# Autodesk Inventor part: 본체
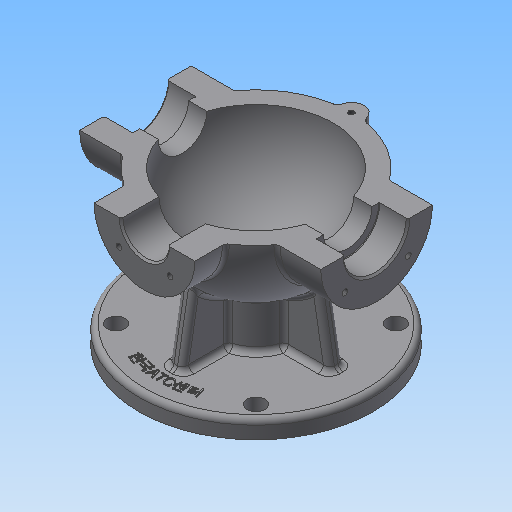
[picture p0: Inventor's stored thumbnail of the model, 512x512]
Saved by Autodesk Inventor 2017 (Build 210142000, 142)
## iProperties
Created: 2015-12
Part Number: 본체
Material: 일반
Document SubType Name: Modeling
Designer: mduedu
Density: 2.71 g/cm^3
Appearance: 기본값
Author: mduedu
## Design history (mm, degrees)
sketch "스케치1"
  geometry: L1 (-53, 0)-(53, 0); A1 r 53 centre (0, 0) between (53, 0) and (-53, 0); 2 further points
  constraints: 2 coincident, 2 end point, 2 point on circle, 1 centre point, 1 horizontal, 1 midpoint
  dimensions: "d0" = 53 radius of A1
revolve "회전1" sketch "스케치1" stored, may be unused: angle "d2" = 90 deg
feature "쉘1" dims "d11" = 10
node "작업 평면1"
sketch "스케치2"
  geometry: C1 r 31 at (0, 0); 1 further point
  constraints: 1 centre point, 1 coincident
  dimensions: "d4" = 62 diameter of C1
extrude "돌출1" join sketch "스케치2" stored distance "d5" = 10; taper "d6" = 0 deg
node "작업 평면2"
sketch "스케치3"
  geometry: C1 r 28 at (0, 0); 1 further point
  constraints: 1 centre point, 1 coincident
  dimensions: "d8" = 56 diameter of C1
extrude "돌출2" join sketch "스케치3" stored distance "d9" = 10; taper "d10" = 0 deg
hole "구멍1" diameter "d14" = 35; stored, may be unused: countersink angle "d18" = 90 deg, drill point angle "d20" = 0 deg; dims "d12" = 10, "d13" = 10, "d15" = 6, "d16" = 4, "d17" = 2, "d19" = 16
hole "구멍2" diameter "d23" = 27; stored, may be unused: countersink angle "d27" = 90 deg, drill point angle "d29" = 0 deg; dims "d21" = 10, "d22" = 10, "d24" = 6, "d25" = 4, "d26" = 2, "d28" = 16
fillet "모깎기1" dims "d30" = 0.3
hole "구멍3" diameter "d33" = 26; stored, may be unused: countersink angle "d37" = 90 deg, drill point angle "d39" = 0 deg; dims "d31" = 10, "d32" = 10, "d34" = 6, "d35" = 4, "d36" = 2, "d38" = 16
chamfer "모따기1" distance "d40" = 1; stored, may be unused: second distance "d41" = 2, angle "d42" = 45 deg
sketch "스케치4"
  geometry: L1 (0, 0)-(0, -25); L2 (0, 0)-(-17.678, -17.678); A1 r 25 centre (0, 0) between (-17.678, -17.678) and (0, -25); 1 further point
  constraints: 4 end point, 2 point on circle, 1 centre point, 1 coincident, 1 vertical
  dimensions: "d43" = 50 diameter of A1; "d47" = 45 deg angle of L1 L2
hole "구멍4" sketch "스케치4" at (-17.678, -17.678) diameter "d49" = 3.242; stored, may be unused: countersink angle "d53" = 90 deg, drill point angle "d55" = 118 deg; dims "d50" = 11, "d51" = 4, "d52" = 2, "d54" = 13
sketch "스케치5"
  geometry: L1 (0, 0)-(0, -20); L2 (0, 0)-(-14.142, -14.142); A1 r 20 centre (0, 0) between (0, -20) and (-14.142, -14.142); 2 further points
  constraints: 4 end point, 2 coincident, 2 point on circle, 1 centre point, 1 vertical
  dimensions: "d59" = 40 diameter of A1; "d65" = 45 deg angle of L1 L2
hole "구멍5" sketch "스케치5" at (-14.142, -14.142) diameter "d67" = 3.242; stored, may be unused: countersink angle "d71" = 90 deg, drill point angle "d73" = 118 deg; dims "d68" = 8, "d69" = 4, "d70" = 2, "d72" = 10
node "작업 평면3"
sketch "스케치6"
  geometry: C1 r 65 at (0, 0); 1 further point
  constraints: 1 centre point, 1 coincident
  dimensions: "d78" = 130 diameter of C1
extrude "돌출3" join sketch "스케치6" distance "d80" = 10; taper "d81" = 0 deg
sketch "스케치7"
  geometry: C1 r 20 at (0, 0); 1 further point
  constraints: 1 centre point, 1 coincident
  dimensions: "d82" = 40 diameter of C1
extrude "돌출4" join sketch "스케치7" stored distance "d84" = 10; taper "d85" = 0 deg
sketch "스케치8"
  geometry: 2 further points
  constraints: 1 coincident
hole "구멍6" sketch "스케치8" at (0, 0) diameter "d86" = 20; stored, may be unused: countersink angle "d90" = 90 deg, drill point angle "d92" = 118 deg; dims "d87" = 7, "d88" = 40, "d89" = 5, "d91" = 10
fillet "모깎기2" dims "d93" = 0.3
sketch "스케치9"
  geometry: L1 (65, -75)-(-65, -75) reference; L2 (-45, -75)-(-38.245, -36.692); A1 r 53 centre (0, 0) between (42.988, 31) and (42.988, -31) reference; 1 further point
  constraints: 2 end point, 1 point on circle, 1 point on line
  dimensions: "d94" = 45 horizontal distance of L2.start point (0, 0); "d95" = 80 deg angle of L2 L1
feature "리브1" sketch "스케치9" dims "d96" = 1, "d97" = 8, "d98" = 0, "d99" = 0, "d100" = 1, "d101" = 1
sketch "스케치10"
  geometry: L1 (0, 0)-(0, -55); L2 (0, 0)-(-38.891, -38.891); A1 r 55 centre (0, 0) between (0, -55) and (-38.891, -38.891); 2 further points
  constraints: 4 end point, 2 coincident, 2 point on circle, 1 centre point, 1 vertical
  dimensions: "d105" = 110 diameter of A1; "d107" = 45 deg angle of L1 L2
hole "구멍7" sketch "스케치10" at (-38.891, -38.891) diameter "d109" = 10; stored, may be unused: countersink angle "d113" = 90 deg, drill point angle "d115" = 118 deg; dims "d110" = 7, "d111" = 40, "d112" = 5, "d114" = 10
fillet "모깎기3" dims "d120" = 3
fillet "모깎기4" dims "d121" = 3, "d122" = 3
fillet "모깎기5" dims "d123" = 3
fillet "모깎기6" dims "d124" = 3
sketch "스케치11"
  geometry: C1 r 5 at (-38.891, 38.891) reference; C2 r 5 at (38.891, 38.891) reference; C3 r 5 at (38.891, -38.891) reference; C4 r 5 at (-38.891, -38.891) reference; C5 r 20 at (0, 0) reference; C6 r 65 at (0, 0) reference; 1 further point
  constraints: 3 other
feature "엠보싱1" sketch "스케치11" dims "d125" = 0.5, "d126" = 0
sketch "스케치12"
  geometry: L1 (0, 100)-(0, -100); L2 (0, 100)-(100, 100); L3 (100, 100)-(100, -100); L4 (100, -100)-(0, -100); 2 further points
  constraints: 8 end point, 3 perpendicular, 1 coincident, 1 midpoint, 1 vertical
  dimensions: "d127" = 200 distance of L2.end L3.end; "d129" = 100 distance between parallel lines of L1 L3
extrude "돌출5" cut sketch "스케치12" stored distance "d130" = 10; taper "d131" = 0 deg
sketch "스케치13"
  geometry: C1 r 7 at (0, 53); A1 r 53 centre (0, 0) between (42.113, 32.179) and (-42.113, 32.179) reference; 1 further point
  constraints: 1 centre point, 1 point on circle
  dimensions: "d132" = 14 diameter of C1
extrude "돌출6" join sketch "스케치13" distance "d134" = 15; taper "d135" = 0 deg
hole "구멍8" diameter "d139" = 3.242; stored, may be unused: countersink angle "d143" = 90 deg, drill point angle "d145" = 118 deg; dims "d140" = 8, "d141" = 4, "d142" = 2, "d144" = 10, "d148" = 10, "d149" = 10
fillet "모깎기7" dims "d146" = 3
fillet "모깎기8" dims "d147" = 3
node "솔리드1"
mirror "대칭1"
mirror "대칭2"
pattern_circular "원형 패턴1" dims angle "d57" = 360 deg
mirror "대칭3"
pattern_circular "원형 패턴2" dims angle "d75" = 360 deg
pattern_circular "원형 패턴3" dims angle "d103" = 360 deg
pattern_circular "원형 패턴4" dims angle "d118" = 360 deg
node "투영된 루프1"
other parameters: "d3" = 67, "d7" = 62, "d77" = -85
